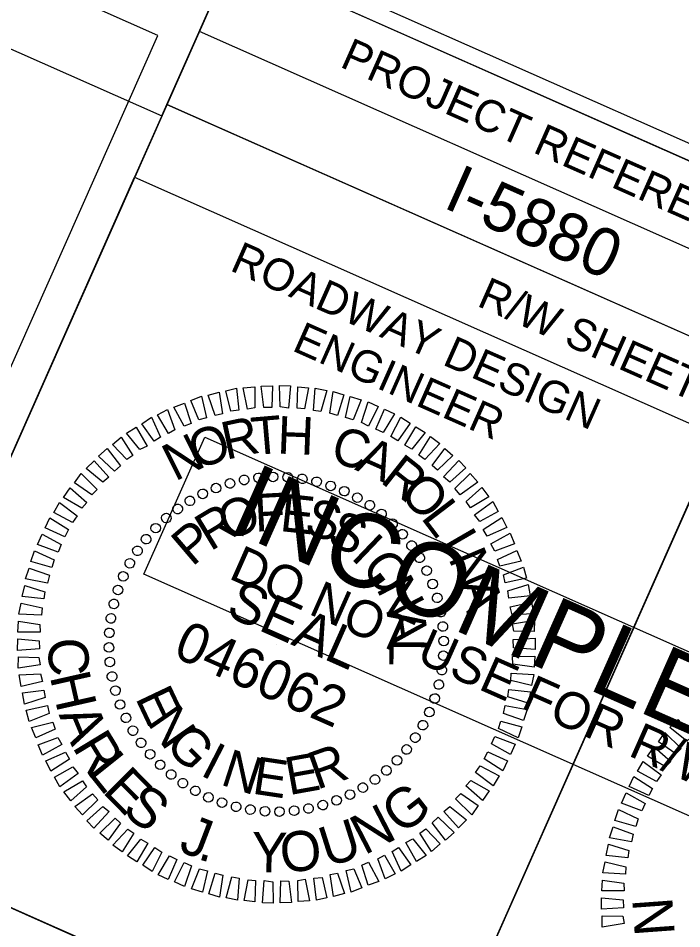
# Model space of a CAD drawing. Extents: x 1637682 to 2864602, y 842496 to 973236.
# Drawn here: x 1639424.2 to 1639528.1, y 843412.4 to 843555.1 of the extents above; entities that cross this region are included whole.
import ezdxf

# ---------------------------------------------------------------- set-up
doc = ezdxf.new("R2010")
doc.units = 0
for name, color, linetype in [('Default', 7, 'Continuous'), ('Old_Level_2', 7, 'Continuous'), ('Prop Dimension Text', 7, 'Continuous'), ('Sheet Clip Boundary CELL', 7, 'Continuous'), ('Sheet Data Field CELL', 7, 'Continuous'), ('Sheet Plan CELL', 7, 'Continuous'), ('Sheet Plot Border Inside CELL', 7, 'Continuous'), ('Sheet Sticker Exception Certification CELL', 7, 'Continuous'), ('Sheet Sticker Incomplete CELL', 7, 'Continuous')]:
    doc.layers.add(name, color=color, linetype=linetype)

msp = doc.modelspace()

# ---------------------------------------------------------------- linework, layer by layer
at = {"layer": 'Old_Level_2'}
for p, q in [((1639459.57, 843482.75), (1639459.57, 843482.75)), ((1639461.87, 843483.08), (1639461.87, 843483.08)), ((1639464.15, 843483.25), (1639464.15, 843483.25)), ((1639466.41, 843483.21), (1639466.41, 843483.21)), ((1639468.67, 843482.93), (1639468.67, 843482.93)), ((1639470.96, 843482.42), (1639470.96, 843482.42)), ((1639455.18, 843481.48), (1639455.18, 843481.48)), ((1639457.38, 843482.25), (1639457.38, 843482.25)), ((1639473.15, 843481.83), (1639473.15, 843481.83)), ((1639475.29, 843480.98), (1639475.29, 843480.98)), ((1639453.1, 843480.6), (1639453.1, 843480.6)), ((1639477.35, 843479.94), (1639477.35, 843479.94)), ((1639449.15, 843478.24), (1639449.15, 843478.24)), ((1639451.09, 843479.46), (1639451.09, 843479.46)), ((1639479.27, 843478.73), (1639479.27, 843478.73)), ((1639447.39, 843476.77), (1639447.39, 843476.77)), ((1639481.11, 843477.44), (1639481.11, 843477.44)), ((1639482.85, 843475.91), (1639482.85, 843475.91)), ((1639445.71, 843475.21), (1639445.71, 843475.21)), ((1639484.41, 843474.23), (1639484.41, 843474.23)), ((1639444.18, 843473.47), (1639444.18, 843473.47)), ((1639485.88, 843472.48), (1639485.88, 843472.48)), ((1639442.89, 843471.63), (1639442.89, 843471.63)), ((1639441.68, 843469.7), (1639441.68, 843469.7)), ((1639487.11, 843470.54), (1639487.11, 843470.54)), ((1639488.24, 843468.53), (1639488.24, 843468.53)), ((1639440.64, 843467.64), (1639440.64, 843467.64)), ((1639439.79, 843465.5), (1639439.79, 843465.5)), ((1639489.13, 843466.45), (1639489.13, 843466.45)), ((1639489.9, 843464.25), (1639489.9, 843464.25)), ((1639439.21, 843463.31), (1639439.21, 843463.31)), ((1639438.7, 843461.03), (1639438.7, 843461.03)), ((1639490.39, 843462.05), (1639490.39, 843462.05)), ((1639490.73, 843459.76), (1639490.73, 843459.76)), ((1639438.42, 843458.76), (1639438.42, 843458.76)), ((1639464.63, 843456.99), (1639464.63, 843456.99)), ((1639490.89, 843457.47), (1639490.89, 843457.47)), ((1639438.38, 843456.51), (1639438.38, 843456.51)), ((1639438.54, 843454.22), (1639438.54, 843454.22)), ((1639490.85, 843455.22), (1639490.85, 843455.22)), ((1639490.57, 843452.95), (1639490.57, 843452.95)), ((1639438.88, 843451.92), (1639438.88, 843451.92)), ((1639439.37, 843449.73), (1639439.37, 843449.73)), ((1639490.06, 843450.67), (1639490.06, 843450.67)), ((1639489.48, 843448.48), (1639489.48, 843448.48)), ((1639440.14, 843447.53), (1639440.14, 843447.53)), ((1639441.03, 843445.45), (1639441.03, 843445.45)), ((1639488.63, 843446.34), (1639488.63, 843446.34)), ((1639487.59, 843444.28), (1639487.59, 843444.28)), ((1639442.16, 843443.44), (1639442.16, 843443.44)), ((1639443.39, 843441.5), (1639443.39, 843441.5)), ((1639486.38, 843442.35), (1639486.38, 843442.35)), ((1639444.86, 843439.75), (1639444.86, 843439.75)), ((1639485.09, 843440.51), (1639485.09, 843440.51)), ((1639483.56, 843438.77), (1639483.56, 843438.77)), ((1639446.42, 843438.07), (1639446.42, 843438.07)), ((1639481.88, 843437.21), (1639481.88, 843437.21)), ((1639448.16, 843436.54), (1639448.16, 843436.54)), ((1639480.12, 843435.74), (1639480.12, 843435.74)), ((1639450, 843435.25), (1639450, 843435.25)), ((1639451.92, 843434.04), (1639451.92, 843434.04)), ((1639478.18, 843434.52), (1639478.18, 843434.52)), ((1639453.98, 843433), (1639453.98, 843433)), ((1639474.09, 843432.5), (1639474.09, 843432.5)), ((1639476.17, 843433.38), (1639476.17, 843433.38)), ((1639456.12, 843432.15), (1639456.12, 843432.15)), ((1639458.31, 843431.56), (1639458.31, 843431.56)), ((1639460.6, 843431.05), (1639460.6, 843431.05)), ((1639469.7, 843431.23), (1639469.7, 843431.23)), ((1639471.89, 843431.72), (1639471.89, 843431.72)), ((1639462.86, 843430.77), (1639462.86, 843430.77)), ((1639465.12, 843430.73), (1639465.12, 843430.73)), ((1639467.4, 843430.9), (1639467.4, 843430.9))]:
    msp.add_line(p, q, dxfattribs=at)
for points in [[(1639457.48, 843493.51), (1639456.73, 843496.72), (1639458.37, 843497.1), (1639458.78, 843493.64)], [(1639460.11, 843493.82), (1639459.42, 843497.17), (1639461.24, 843497.31), (1639461.26, 843494.01)], [(1639462.66, 843494.1), (1639462.26, 843497.45), (1639464.04, 843497.49), (1639463.91, 843494.08)], [(1639465.21, 843494.21), (1639465.14, 843497.54), (1639466.83, 843497.5), (1639466.54, 843493.99)], [(1639467.9, 843493.99), (1639468.01, 843497.34), (1639469.69, 843497.15), (1639469.05, 843493.9)], [(1639470.47, 843493.63), (1639470.74, 843497.1), (1639472.52, 843496.74), (1639471.59, 843493.45)], [(1639452.48, 843492.16), (1639451.26, 843495.17), (1639452.9, 843495.84), (1639453.68, 843492.45)], [(1639455.04, 843492.84), (1639453.94, 843496.02), (1639455.67, 843496.49), (1639456.22, 843493.08)], [(1639473.01, 843493.19), (1639473.54, 843496.6), (1639475.19, 843496.07), (1639474.23, 843492.84)], [(1639475.44, 843492.5), (1639476.22, 843495.81), (1639477.94, 843495.31), (1639476.66, 843492.15)], [(1639450.18, 843491.14), (1639448.56, 843494.16), (1639450.23, 843494.76), (1639451.27, 843491.59)], [(1639477.95, 843491.72), (1639479.04, 843494.95), (1639480.6, 843494.23), (1639479.09, 843491.18)], [(1639480.24, 843490.7), (1639481.57, 843493.83), (1639483.14, 843493.11), (1639481.38, 843490.16)], [(1639445.5, 843488.81), (1639443.59, 843491.54), (1639445.1, 843492.55), (1639446.51, 843489.46)], [(1639447.72, 843490.03), (1639446.01, 843492.96), (1639447.6, 843493.77), (1639448.76, 843490.61)], [(1639482.59, 843489.53), (1639484.11, 843492.58), (1639485.57, 843491.62), (1639483.67, 843488.85)], [(1639443.24, 843487.49), (1639441.15, 843490.08), (1639442.69, 843491.02), (1639444.38, 843488.03)], [(1639484.74, 843488.17), (1639486.48, 843491.07), (1639487.96, 843490.16), (1639485.84, 843487.54)], [(1639486.97, 843486.6), (1639488.78, 843489.53), (1639490.25, 843488.45), (1639487.88, 843485.94)], [(1639441.21, 843485.91), (1639438.97, 843488.27), (1639440.33, 843489.46), (1639442.17, 843486.58)], [(1639439.31, 843484.1), (1639436.79, 843486.47), (1639438.14, 843487.66), (1639440.24, 843484.96)], [(1639489.02, 843485), (1639491, 843487.68), (1639492.29, 843486.57), (1639489.89, 843484.24)], [(1639437.45, 843482.39), (1639434.83, 843484.52), (1639436.09, 843485.75), (1639438.41, 843483.18)], [(1639490.82, 843483.22), (1639493.21, 843485.78), (1639494.32, 843484.64), (1639491.79, 843482.41)], [(1639435.75, 843480.38), (1639433.03, 843482.27), (1639434.04, 843483.72), (1639436.56, 843481.23)], [(1639492.6, 843481.39), (1639495.01, 843483.72), (1639496.21, 843482.41), (1639493.44, 843480.41)], [(1639434.15, 843478.33), (1639431.32, 843479.98), (1639432.35, 843481.48), (1639434.96, 843479.18)], [(1639494.35, 843479.34), (1639496.81, 843481.54), (1639497.91, 843480.11), (1639495.02, 843478.38)], [(1639432.72, 843476.04), (1639429.76, 843477.63), (1639430.65, 843479.19), (1639433.45, 843477.1)], [(1639495.68, 843477.25), (1639498.54, 843479.33), (1639499.37, 843477.79), (1639496.49, 843476.22)], [(1639431.51, 843473.83), (1639428.42, 843475.25), (1639429.18, 843476.8), (1639432.09, 843474.95)], [(1639497.04, 843474.97), (1639499.94, 843476.86), (1639500.75, 843475.27), (1639497.67, 843473.91)], [(1639430.44, 843471.44), (1639427.25, 843472.62), (1639427.94, 843474.26), (1639430.93, 843472.6)], [(1639498.24, 843472.7), (1639501.27, 843474.37), (1639501.94, 843472.73), (1639498.85, 843471.59)], [(1639429.47, 843469.01), (1639426.18, 843469.95), (1639426.77, 843471.63), (1639429.86, 843470.21)], [(1639499.26, 843470.28), (1639502.29, 843471.67), (1639502.96, 843470.03), (1639499.66, 843469.21)], [(1639428.78, 843466.58), (1639425.37, 843467.23), (1639425.91, 843468.93), (1639429.08, 843467.82)], [(1639500.21, 843467.84), (1639503.35, 843469.07), (1639503.81, 843467.34), (1639500.48, 843466.59)], [(1639428.24, 843464.09), (1639424.82, 843464.45), (1639425.22, 843466.21), (1639428.38, 843465.22)], [(1639500.87, 843465.35), (1639504.08, 843466.37), (1639504.41, 843464.59), (1639501.06, 843464.19)], [(1639427.84, 843461.53), (1639424.29, 843461.72), (1639424.67, 843463.44), (1639427.93, 843462.68)], [(1639501.28, 843462.84), (1639504.61, 843463.59), (1639504.91, 843461.76), (1639501.55, 843461.6)], [(1639427.63, 843458.89), (1639424.16, 843458.88), (1639424.27, 843460.6), (1639427.58, 843460.11)], [(1639501.64, 843460.2), (1639505.05, 843460.74), (1639505.04, 843458.98), (1639501.83, 843459.04)], [(1639427.54, 843456.26), (1639424.09, 843456.02), (1639424.12, 843457.82), (1639427.51, 843457.53)], [(1639501.73, 843457.72), (1639505.18, 843457.96), (1639505.15, 843456.15), (1639501.76, 843456.45)], [(1639427.63, 843453.78), (1639424.22, 843453.24), (1639424.23, 843455), (1639427.44, 843454.94)], [(1639501.64, 843455.09), (1639505.11, 843455.1), (1639505, 843453.38), (1639501.69, 843453.87)], [(1639501.43, 843452.45), (1639504.98, 843452.25), (1639504.6, 843450.54), (1639501.34, 843451.3)], [(1639427.99, 843451.14), (1639424.66, 843450.38), (1639424.36, 843452.22), (1639427.72, 843452.38)], [(1639428.4, 843448.63), (1639425.19, 843447.61), (1639424.86, 843449.39), (1639428.21, 843449.79)], [(1639501.03, 843449.89), (1639504.45, 843449.53), (1639504.05, 843447.77), (1639500.89, 843448.76)], [(1639429.06, 843446.14), (1639425.92, 843444.91), (1639425.46, 843446.64), (1639428.79, 843447.39)], [(1639500.49, 843447.4), (1639503.9, 843446.75), (1639503.36, 843445.05), (1639500.19, 843446.16)], [(1639430.01, 843443.7), (1639426.98, 843442.31), (1639426.31, 843443.95), (1639429.61, 843444.77)], [(1639499.8, 843444.96), (1639503.09, 843444.03), (1639502.5, 843442.35), (1639499.41, 843443.77)], [(1639528.91, 843441.83), (1639526.29, 843443.96), (1639527.55, 843445.19), (1639529.87, 843442.62)], [(1639498.83, 843442.54), (1639502.02, 843441.36), (1639501.33, 843439.72), (1639498.34, 843441.38)], [(1639527.21, 843439.83), (1639524.49, 843441.72), (1639525.5, 843443.16), (1639528.02, 843440.68)], [(1639431.03, 843441.28), (1639428, 843439.61), (1639427.33, 843441.25), (1639430.42, 843442.39)], [(1639432.23, 843439.01), (1639429.33, 843437.12), (1639428.52, 843438.7), (1639431.6, 843440.07)], [(1639497.76, 843440.15), (1639500.85, 843438.73), (1639500.09, 843437.18), (1639497.18, 843439.03)], [(1639525.61, 843437.78), (1639522.78, 843439.43), (1639523.81, 843440.92), (1639526.42, 843438.63)], [(1639524.18, 843435.49), (1639521.22, 843437.08), (1639522.11, 843438.64), (1639524.91, 843436.54)], [(1639433.59, 843436.73), (1639430.73, 843434.65), (1639429.9, 843436.19), (1639432.78, 843437.76)], [(1639496.55, 843437.94), (1639499.51, 843436.35), (1639498.62, 843434.79), (1639495.82, 843436.88)], [(1639434.92, 843434.64), (1639432.46, 843432.44), (1639431.36, 843433.87), (1639434.25, 843435.6)], [(1639495.12, 843435.64), (1639497.95, 843434), (1639496.92, 843432.5), (1639494.31, 843434.8)], [(1639522.96, 843433.28), (1639519.87, 843434.7), (1639520.64, 843436.25), (1639523.55, 843434.39)], [(1639436.67, 843432.59), (1639434.26, 843430.26), (1639433.06, 843431.57), (1639435.83, 843433.57)], [(1639493.52, 843433.6), (1639496.24, 843431.71), (1639495.23, 843430.26), (1639492.71, 843432.75)], [(1639521.9, 843430.89), (1639518.71, 843432.07), (1639519.4, 843433.71), (1639522.39, 843432.05)], [(1639438.45, 843430.76), (1639436.06, 843428.2), (1639434.95, 843429.34), (1639437.48, 843431.57)], [(1639491.82, 843431.59), (1639494.44, 843429.46), (1639493.18, 843428.23), (1639490.86, 843430.8)], [(1639520.93, 843428.46), (1639517.64, 843429.4), (1639518.23, 843431.08), (1639521.32, 843429.66)], [(1639440.25, 843428.98), (1639438.27, 843426.3), (1639436.98, 843427.41), (1639439.38, 843429.74)], [(1639489.96, 843429.88), (1639492.48, 843427.51), (1639491.13, 843426.32), (1639489.03, 843429.02)], [(1639520.24, 843426.03), (1639516.83, 843426.68), (1639517.37, 843428.37), (1639520.54, 843427.26)], [(1639442.3, 843427.38), (1639440.49, 843424.45), (1639439.02, 843425.53), (1639441.39, 843428.04)], [(1639488.06, 843428.07), (1639490.3, 843425.71), (1639488.94, 843424.52), (1639487.1, 843427.4)], [(1639444.53, 843425.81), (1639442.79, 843422.91), (1639441.31, 843423.82), (1639443.43, 843426.44)], [(1639486.03, 843426.49), (1639488.12, 843423.9), (1639486.58, 843422.96), (1639484.89, 843425.95)], [(1639519.7, 843423.53), (1639516.28, 843423.9), (1639516.68, 843425.66), (1639519.84, 843424.67)], [(1639446.68, 843424.44), (1639445.16, 843421.4), (1639443.7, 843422.36), (1639445.6, 843425.13)], [(1639481.55, 843423.95), (1639483.26, 843421.02), (1639481.67, 843420.21), (1639480.51, 843423.37)], [(1639483.77, 843425.17), (1639485.68, 843422.44), (1639484.17, 843421.43), (1639482.76, 843424.52)], [(1639449.03, 843423.28), (1639447.7, 843420.15), (1639446.13, 843420.87), (1639447.89, 843423.82)], [(1639451.32, 843422.26), (1639450.23, 843419.02), (1639448.67, 843419.74), (1639450.18, 843422.79)], [(1639479.09, 843422.84), (1639480.71, 843419.82), (1639479.04, 843419.22), (1639478, 843422.39)], [(1639519.3, 843420.98), (1639515.75, 843421.17), (1639516.13, 843422.88), (1639519.39, 843422.13)], [(1639453.83, 843421.48), (1639453.05, 843418.17), (1639451.33, 843418.67), (1639452.61, 843421.82)], [(1639456.26, 843420.79), (1639455.73, 843417.38), (1639454.08, 843417.91), (1639455.04, 843421.14)], [(1639474.23, 843421.14), (1639475.33, 843417.96), (1639473.6, 843417.49), (1639473.05, 843420.9)], [(1639476.79, 843421.82), (1639478.01, 843418.81), (1639476.37, 843418.14), (1639475.59, 843421.53)], [(1639458.8, 843420.34), (1639458.53, 843416.88), (1639456.75, 843417.24), (1639457.68, 843420.53)], [(1639461.37, 843419.99), (1639461.26, 843416.64), (1639459.58, 843416.83), (1639460.22, 843420.08)], [(1639464.06, 843419.77), (1639464.13, 843416.44), (1639462.44, 843416.48), (1639462.73, 843419.99)], [(1639466.61, 843419.88), (1639467.01, 843416.53), (1639465.23, 843416.49), (1639465.36, 843419.9)], [(1639469.16, 843420.16), (1639469.85, 843416.81), (1639468.03, 843416.67), (1639468.01, 843419.97)], [(1639471.79, 843420.47), (1639472.54, 843417.26), (1639470.9, 843416.88), (1639470.49, 843420.34)], [(1639519.09, 843418.34), (1639515.62, 843418.33), (1639515.73, 843420.05), (1639519.04, 843419.55)], [(1639519, 843415.71), (1639515.55, 843415.46), (1639515.57, 843417.27), (1639518.97, 843416.97)], [(1639519.09, 843413.23), (1639515.68, 843412.68), (1639515.68, 843414.44), (1639518.9, 843414.39)]]:
    msp.add_lwpolyline(points, close=True, dxfattribs=at)
for centre, major_axis in [((1639461.85, 843483.07), (-0.08, 0.749)), ((1639464.14, 843483.21), (-0.014, 0.753)), ((1639466.42, 843483.16), (0.051, 0.751)), ((1639457.37, 843482.19), (-0.209, 0.723)), ((1639459.59, 843482.73), (-0.145, 0.739)), ((1639468.7, 843482.9), (0.117, 0.744)), ((1639470.94, 843482.45), (0.181, 0.731)), ((1639473.14, 843481.8), (0.244, 0.712)), ((1639453.1, 843480.55), (-0.331, 0.676)), ((1639455.2, 843481.46), (-0.271, 0.703)), ((1639475.27, 843480.97), (0.305, 0.688)), ((1639451.09, 843479.45), (-0.389, 0.645)), ((1639477.32, 843479.95), (0.364, 0.659)), ((1639479.27, 843478.76), (0.42, 0.625)), ((1639449.19, 843478.18), (-0.443, 0.608)), ((1639481.11, 843477.4), (0.473, 0.586)), ((1639447.4, 843476.76), (-0.495, 0.568)), ((1639482.83, 843475.88), (0.522, 0.542)), ((1639445.74, 843475.18), (-0.542, 0.522)), ((1639444.23, 843473.46), (-0.586, 0.473)), ((1639484.4, 843474.23), (0.568, 0.495)), ((1639442.87, 843471.62), (-0.625, 0.42)), ((1639485.83, 843472.44), (0.608, 0.443)), ((1639487.1, 843470.53), (0.645, 0.389)), ((1639441.68, 843469.67), (-0.659, 0.364)), ((1639440.66, 843467.62), (-0.688, 0.305)), ((1639488.19, 843468.52), (0.676, 0.331)), ((1639489.11, 843466.43), (0.703, 0.271)), ((1639439.82, 843465.49), (-0.712, 0.244)), ((1639439.18, 843463.3), (-0.731, 0.181)), ((1639489.84, 843464.26), (0.723, 0.209)), ((1639490.37, 843462.03), (0.739, 0.145)), ((1639438.72, 843461.05), (-0.744, 0.117)), ((1639438.47, 843458.78), (-0.751, 0.051)), ((1639490.71, 843459.77), (0.749, 0.08)), ((1639490.86, 843457.49), (0.753, 0.014)), ((1639438.41, 843456.49), (-0.753, -0.014)), ((1639490.8, 843455.2), (0.751, -0.051)), ((1639438.56, 843454.21), (-0.749, -0.08)), ((1639438.9, 843451.95), (-0.739, -0.145)), ((1639490.55, 843452.93), (0.744, -0.117)), ((1639490.09, 843450.68), (0.731, -0.181)), ((1639439.43, 843449.72), (-0.723, -0.209)), ((1639440.16, 843447.55), (-0.703, -0.271)), ((1639489.45, 843448.49), (0.712, -0.244)), ((1639488.61, 843446.36), (0.688, -0.305)), ((1639441.08, 843445.46), (-0.676, -0.331)), ((1639442.17, 843443.45), (-0.645, -0.389)), ((1639487.59, 843444.31), (0.659, -0.364)), ((1639486.4, 843442.36), (0.625, -0.42)), ((1639443.44, 843441.54), (-0.608, -0.443)), ((1639485.04, 843440.51), (0.586, -0.473)), ((1639444.87, 843439.75), (-0.568, -0.495)), ((1639483.53, 843438.8), (0.542, -0.522)), ((1639446.44, 843438.1), (-0.522, -0.542)), ((1639448.16, 843436.58), (-0.473, -0.586)), ((1639481.87, 843437.22), (0.495, -0.568)), ((1639450, 843435.22), (-0.42, -0.625)), ((1639478.18, 843434.53), (0.389, -0.645)), ((1639480.08, 843435.79), (0.443, -0.608)), ((1639451.95, 843434.03), (-0.364, -0.659)), ((1639476.17, 843433.43), (0.331, -0.676)), ((1639454, 843433.01), (-0.305, -0.688)), ((1639456.13, 843432.18), (-0.244, -0.712)), ((1639471.9, 843431.79), (0.209, -0.723)), ((1639474.07, 843432.52), (0.271, -0.703)), ((1639458.33, 843431.53), (-0.181, -0.731)), ((1639460.57, 843431.08), (-0.117, -0.744)), ((1639462.85, 843430.82), (-0.051, -0.751)), ((1639465.13, 843430.77), (0.014, -0.753)), ((1639467.42, 843430.91), (0.08, -0.749)), ((1639469.68, 843431.25), (0.145, -0.739))]:
    msp.add_ellipse(centre, major_axis=major_axis, ratio=0.999708, dxfattribs=at)
at = {"layer": 'Prop Dimension Text'}
msp.add_lwpolyline([(1639309.54, 843600.57), (1639446.69, 843539.76), (1639457.67, 843564.51), (1639320.52, 843625.32)], close=True, dxfattribs=at)
at = {"layer": 'Sheet Clip Boundary CELL'}
msp.add_lwpolyline([(1638095.26, 843695.55), (1638010.34, 843303.19), (1637949.73, 843324.57), (1637886.34, 843167.39), (1638760.91, 842777.56), (1638750.92, 842749.91), (1638861.21, 842700.69), (1639015.67, 842665.82), (1639189.46, 842589.52), (1639522.76, 843341.19), (1639380.4, 843404.31), (1639446.06, 843552.39), (1639089.07, 843710.68), (1638988.3, 843567.43), (1638956.05, 843552.43), (1638629.84, 843695.47), (1638719.07, 843884.38), (1638267, 844086.34)], close=True, dxfattribs=at)
at = {"layer": 'Sheet Plan CELL'}
for p, q in [((1639452.57, 843553.04), (1639635.44, 843471.94)), ((1639447.5, 843541.57), (1639442.43, 843530.16)), ((1639447.5, 843541.57), (1639630.37, 843460.51)), ((1639447.5, 843541.57), (1639630.37, 843460.51)), ((1639533.9, 843489.6), (1639488.32, 843386.79))]:
    msp.add_line(p, q, dxfattribs=at)
for points in [[(1639640.56, 843483.39), (1638269.28, 844091.43), (1637843.67, 843131.56), (1639214.92, 842523.53)], [(1637843.67, 843131.56), (1638269.25, 844091.42), (1639457.67, 843564.51), (1639396.85, 843427.32), (1639579.71, 843346.22), (1639214.92, 842523.53)], [(1639457.67, 843564.51), (1639640.56, 843483.39), (1639630.37, 843460.51), (1639447.5, 843541.57)], [(1639442.43, 843530.16), (1639533.9, 843489.6), (1639488.29, 843386.75), (1639396.85, 843427.32)], [(1639533.9, 843489.6), (1639625.31, 843449.08), (1639579.71, 843346.22), (1639488.29, 843386.75)]]:
    msp.add_lwpolyline(points, close=True, dxfattribs=at)
at = {"layer": 'Sheet Plot Border Inside CELL'}
msp.add_lwpolyline([(1637702.34, 843191.48), (1639225.33, 842516.19), (1639652.97, 843480.61), (1638129.98, 844155.92)], close=True, dxfattribs=at)
at = {"layer": 'Sheet Sticker Exception Certification CELL'}
msp.add_line((1639396.85, 843427.32), (1639579.72, 843346.23), dxfattribs=at)
msp.add_line((1639396.85, 843427.32), (1639579.72, 843346.23), dxfattribs=at)
at = {"layer": 'Sheet Sticker Incomplete CELL'}
msp.add_lwpolyline([(1639443.9, 843467.97), (1639453.43, 843489.46), (1639587.81, 843429.87), (1639578.29, 843408.39)], close=True, dxfattribs=at)

# ---------------------------------------------------------------- texts
at = {"layer": 'Default'}
for s, rotation, p in [('C', 273.287, (1639428.79, 843457.86)), ('H', 282.7308, (1639429.13, 843451.97)), ('A', 292.5706, (1639430.51, 843445.97)), ('R', 301.2832, (1639432.57, 843440.93)), ('L', 308.6554, (1639434.89, 843436.95)), ('E', 314.8396, (1639437.22, 843433.86)), ('S', 321.8463, (1639440.25, 843430.69)), ('G', 37.8869, (1639484.26, 843426.96)), ('N', 27.316, (1639478.42, 843423.87)), ('J', 339.1192, (1639449.15, 843424.63)), ('U', 17.5219, (1639472.59, 843422.01)), ('Y', 358.3297, (1639460.65, 843421.34)), ('O', 6.1284, (1639465.52, 843421.13)), ('.', 344.3011, (1639452.13, 843423.37)), ('N', 274.1644, (1639520.36, 843417.08))]:
    msp.add_text(s, height=6.27, rotation=rotation, dxfattribs=at).set_placement(p)
at = {"layer": 'Old_Level_2'}
for s, height, rotation, p in [('R', 5.9, 12.1076, (1639456.75, 843485.87)), ('T', 5.9, 4.9069, (1639460.92, 843486.6)), ('H', 5.9, 357.7066, (1639464.72, 843486.87)), ('O', 5.9, 19.3089, (1639452.16, 843484.29)), ('N', 5.9, 26.5106, (1639448.76, 843482.43)), ('C', 5.9, 343.307, (1639472.85, 843485.7)), ('A', 5.9, 336.1075, (1639476.78, 843484.38)), ('R', 5.9, 321.7082, (1639480.75, 843482.48)), ('O', 5.9, 314.5083, (1639483.67, 843480.39)), ('O', 5.9, 21.7684, (1639456.97, 843473.11)), ('F', 5.9, 3.0542, (1639461.35, 843474.61)), ('E', 5.9, 353.6982, (1639465.05, 843474.75)), ('S', 5.9, 344.3427, (1639468.8, 843474.36)), ('L', 5.9, 307.308, (1639487.15, 843476.82)), ('R', 5.9, 31.1268, (1639454.29, 843471.47)), ('S', 5.9, 334.9875, (1639472.29, 843472.94)), ('P', 5.9, 40.486, (1639451.45, 843469.04)), ('I', 5.9, 316.2767, (1639476.14, 843470.52)), ('I', 5.9, 300.1073, (1639490.08, 843472.86)), ('O', 5.9, 306.9206, (1639477.78, 843469.03)), ('N', 5.9, 292.906, (1639491.52, 843470.49)), ('N', 5.9, 297.5638, (1639480.2, 843465.74)), ('SEAL', 6.273, 336.0871, (1639456.52, 843461.56)), ('A', 5.9, 285.7043, (1639493.16, 843466.45)), ('A', 5.9, 278.8474, (1639481.88, 843462.07)), ('046062', 6.275, 336.0871, (1639448.24, 843455.16)), ('L', 5.9, 269.488, (1639482.36, 843457.96)), ('E', 5.9, 295.364, (1639442.47, 843448.59)), ('N', 5.9, 304.7211, (1639444.26, 843444.77)), ('G', 5.9, 314.0774, (1639447, 843441.06)), ('I', 5.9, 332.7883, (1639452.54, 843436.56)), ('R', 5.9, 19.5685, (1639470.99, 843434.15)), ('N', 5.9, 342.1435, (1639455.7, 843435.05)), ('E', 5.9, 10.2112, (1639466.61, 843433.33)), ('E', 5.9, 351.4989, (1639460.71, 843433.61))]:
    msp.add_text(s, height=height, rotation=rotation, dxfattribs=at).set_placement(p)
at = {"layer": 'Sheet Data Field CELL'}
msp.add_text('I-5880', height=7.5, rotation=336.0871, dxfattribs=at).set_placement((1639490.55, 843525.5))
at = {"layer": 'Sheet Plan CELL'}
for s, height, p in [('PROJECT REFERENCE NO.', 5.0001, (1639474.42, 843547.53)), ('ROADWAY DESIGN', 5.0001, (1639457.19, 843515.63)), ('R/W SHEET NO.', 5.0001, (1639495.88, 843510.07)), ('ENGINEER', 5, (1639466.92, 843503.07))]:
    msp.add_text(s, height=height, rotation=336.0871, dxfattribs=at).set_placement(p)
at = {"layer": 'Sheet Sticker Exception Certification CELL'}
msp.add_text('DOCUMENT NOT CONSIDERED FINAL', height=5.5, rotation=336.0871, dxfattribs=at).set_placement((1639411.92, 843409.32))
msp.add_text('DOCUMENT NOT CONSIDERED FINAL', height=5.5, rotation=336.0871, dxfattribs=at).set_placement((1639411.92, 843409.32))
at = {"layer": 'Sheet Sticker Incomplete CELL'}
for s, height, p in [('INCOMPLETE PLANS', 11.52, (1639456.83, 843475.04)), ('DO NOT USE FOR R/W ACQUISITION', 5.76, (1639456.98, 843467.37))]:
    msp.add_text(s, height=height, rotation=336.0871, dxfattribs=at).set_placement(p)

doc.saveas('drawing.dxf')
